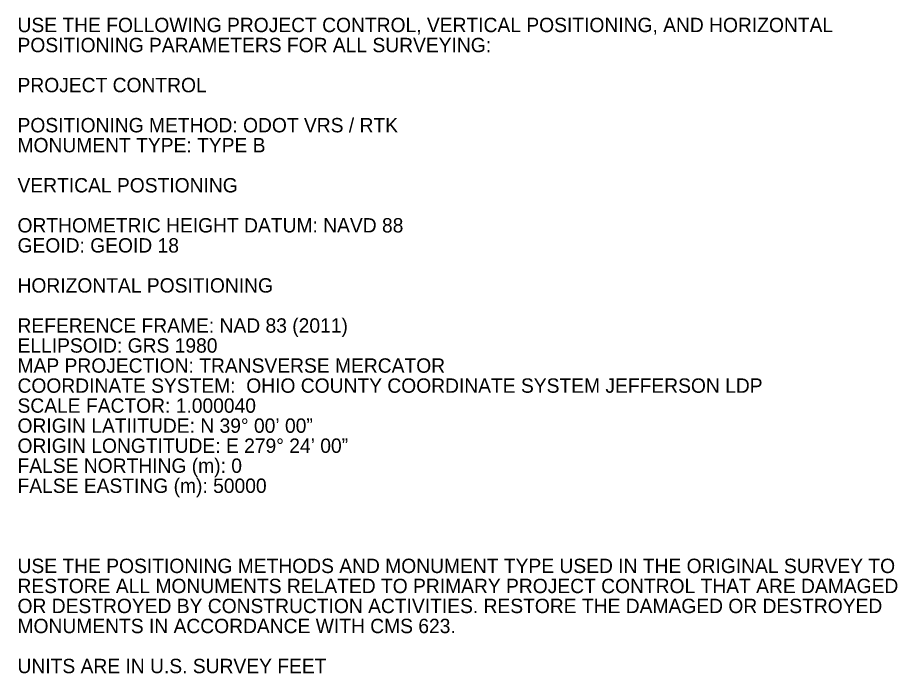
# Model space of a CAD drawing. Extents: x 125846 to 132549, y 511012 to 513420.
# Drawn here: x 126911.4 to 127033.7, y 512664.1 to 512755.3 of the extents above; entities that cross this region are included whole.
import ezdxf

# ---------------------------------------------------------------- set-up
doc = ezdxf.new("R2010")
doc.units = 0
doc.layers.add('SV_X_Text', color=7, linetype='Continuous')

msp = doc.modelspace()

# ---------------------------------------------------------------- texts
at = {"layer": 'SV_X_Text'}
for s, p in [('USE THE FOLLOWING PROJECT CONTROL, VERTICAL POSITIONING, AND HORIZONTAL', (126911.43, 512753.32)), ('POSITIONING PARAMETERS FOR ALL SURVEYING:', (126911.43, 512750.53)), ('PROJECT CONTROL', (126911.43, 512744.96)), ('POSITIONING METHOD: ODOT VRS / RTK', (126911.43, 512739.38)), ('MONUMENT TYPE: TYPE B', (126911.43, 512736.6)), ('VERTICAL POSTIONING', (126911.43, 512731.02)), ('ORTHOMETRIC HEIGHT DATUM: NAVD 88', (126911.43, 512725.45)), ('GEOID: GEOID 18', (126911.43, 512722.66)), ('HORIZONTAL POSITIONING', (126911.43, 512717.09)), ('REFERENCE FRAME: NAD 83 (2011)', (126911.43, 512711.51)), ('ELLIPSOID: GRS 1980', (126911.43, 512708.73)), ('MAP PROJECTION: TRANSVERSE MERCATOR', (126911.43, 512705.94)), ('COORDINATE SYSTEM:  OHIO COUNTY COORDINATE SYSTEM JEFFERSON LDP', (126911.43, 512703.15)), ('SCALE FACTOR: 1.000040', (126911.43, 512700.37)), ('ORIGIN LATIITUDE: N 39° 00’ 00”', (126911.43, 512697.58)), ('ORIGIN LONGTITUDE: E 279° 24’ 00”', (126911.43, 512694.79)), ('FALSE NORTHING (m): 0', (126911.43, 512692.01)), ('FALSE EASTING (m): 50000', (126911.43, 512689.22)), ('USE THE POSITIONING METHODS AND MONUMENT TYPE USED IN THE ORIGINAL SURVEY TO', (126911.43, 512678.07)), ('RESTORE ALL MONUMENTS RELATED TO PRIMARY PROJECT CONTROL THAT ARE DAMAGED', (126911.43, 512675.28)), ('OR DESTROYED BY CONSTRUCTION ACTIVITIES. RESTORE THE DAMAGED OR DESTROYED', (126911.43, 512672.5)), ('MONUMENTS IN ACCORDANCE WITH CMS 623.', (126911.43, 512669.71)), ('UNITS ARE IN U.S. SURVEY FEET', (126911.43, 512664.14))]:
    msp.add_text(s, height=2, dxfattribs=at).set_placement(p)

doc.saveas('drawing.dxf')
